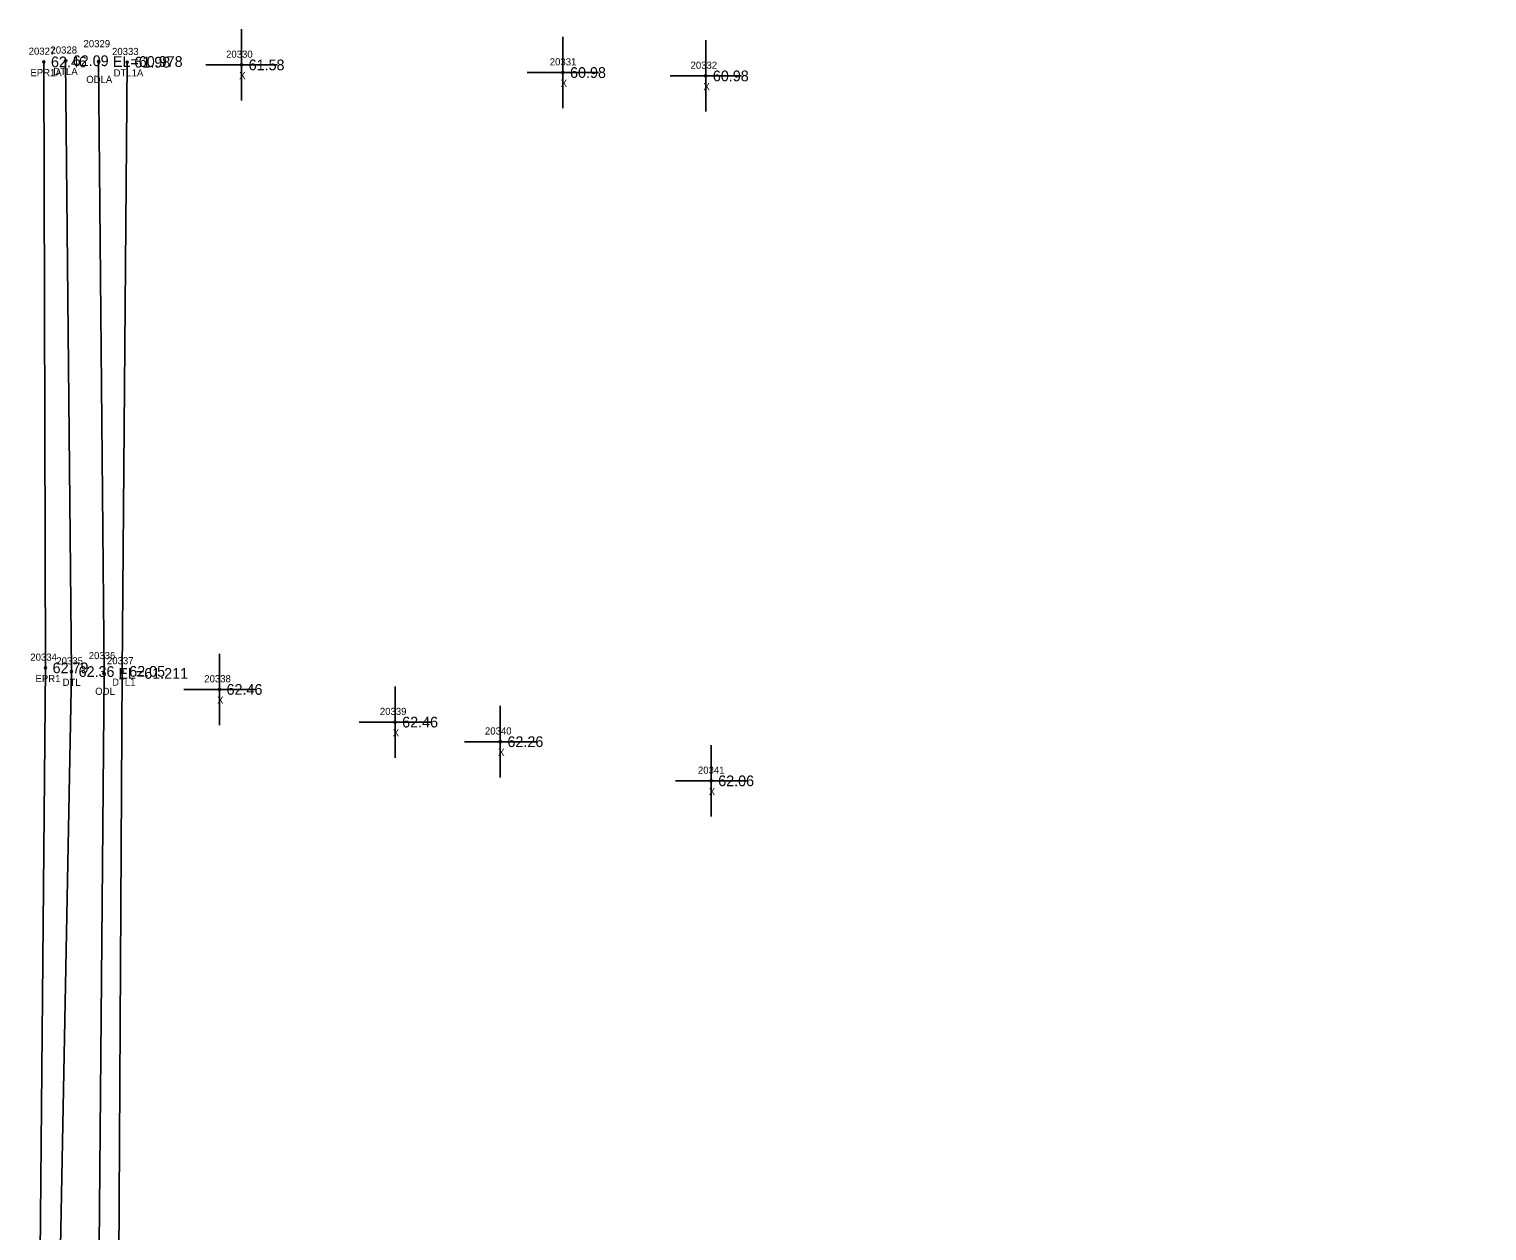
# Model space of a CAD drawing. Extents: x 2420351 to 2422725, y 845330 to 846558.
# Drawn here: x 2420970.4 to 2421174.5, y 846026.9 to 846195 of the extents above; entities that cross this region are included whole.
import ezdxf

# ---------------------------------------------------------------- set-up
doc = ezdxf.new("R2010")
doc.units = 0
for name, color, linetype in [('RD_EX_H2O', 7, 'Continuous'), ('RD_EX_H2O_txCode', 7, 'Continuous'), ('RD_EX_Misc', 7, 'Continuous'), ('RD_EX_Misc_txCode', 7, 'Continuous'), ('RD_EX_Road', 7, 'Continuous'), ('RD_EX_Road_txCode', 7, 'Continuous'), ('RD_EX_TX_H2O_ELEV', 7, 'Continuous'), ('RD_EX_TX_Misc_ELEV', 7, 'Continuous'), ('RD_EX_TX_Road_ELEV', 7, 'Continuous'), ('RD_SMD_Locator', 7, 'Continuous')]:
    doc.layers.add(name, color=color, linetype=linetype)

msp = doc.modelspace()

# ---------------------------------------------------------------- linework, layer by layer
at = {"layer": 'RD_EX_H2O'}
for points in [[(2420975.55, 846190.58), (2420976.37, 846105.11), (2420974.31, 845997.82), (2420976.03, 845896.74), (2420974.59, 845794.18), (2420975.37, 845743.63), (2420984.12, 845720.99), (2420999.91, 845711.18), (2421116.7, 845699.77), (2421177.35, 845696.01), (2421236.57, 845694.11), (2421292.07, 845694.75), (2421349.67, 845700.43), (2421411.57, 845706.56), (2421470.63, 845718.76), (2421529.96, 845732.93), (2421551.14, 845737.51), (2421602.97, 845753.33), (2421656.85, 845776.48), (2421724.45, 845805.15), (2421739.21, 845812.56)], [(2420980.17, 846190.47), (2420980.93, 846104.85), (2420980.02, 845997.99), (2420979.17, 845896.92), (2420978.72, 845794), (2420978.72, 845743.89), (2420987.58, 845724.3), (2421000.53, 845717.13), (2421117.24, 845704.33), (2421178.3, 845699.94), (2421237.1, 845697.97), (2421292.37, 845698.66), (2421349.43, 845702.84), (2421410.88, 845710.25), (2421469.94, 845721.7), (2421529.19, 845736.54), (2421550.26, 845742.27), (2421602, 845757.38), (2421655.89, 845778.44), (2421721.41, 845810.89), (2421742.22, 845823.45)], [(2420984.17, 846190.38), (2420983.45, 846105.14), (2420982.87, 845998.03), (2420982.41, 845897.21), (2420981.52, 845793.93), (2420982.23, 845744.07), (2420990.87, 845727.81), (2421002.71, 845721.72), (2421118.19, 845709.67), (2421178.8, 845706.59), (2421237.43, 845704.42), (2421292.29, 845705.88), (2421348.44, 845711.4), (2421408.11, 845718.43)]]:
    msp.add_lwpolyline(points, dxfattribs=at)
at = {"layer": 'RD_EX_Misc'}
for p, q in [((2421000.17, 846185), (2421000.17, 846195)), ((2421045.16, 846183.93), (2421045.16, 846193.93)), ((2421065.15, 846183.46), (2421065.15, 846193.46)), ((2420995.17, 846190), (2421005.17, 846190)), ((2421040.16, 846188.93), (2421050.16, 846188.93)), ((2421060.15, 846188.46), (2421070.15, 846188.46)), ((2420997.08, 846097.61), (2420997.08, 846107.61)), ((2420992.08, 846102.61), (2421002.08, 846102.61)), ((2421021.66, 846093.04), (2421021.66, 846103.04)), ((2421036.4, 846090.3), (2421036.4, 846100.3)), ((2421016.66, 846098.04), (2421026.66, 846098.04)), ((2421031.4, 846095.3), (2421041.4, 846095.3)), ((2421065.9, 846084.82), (2421065.9, 846094.82)), ((2421060.9, 846089.82), (2421070.9, 846089.82))]:
    msp.add_line(p, q, dxfattribs=at)
at = {"layer": 'RD_EX_Road'}
msp.add_lwpolyline([(2420972.5, 846190.42), (2420972.73, 846105.63), (2420971.77, 845998.07), (2420972.4, 845896.57), (2420972.04, 845794.22), (2420971.47, 845746.74), (2420974.33, 845731.55), (2420982.05, 845718.86), (2420998.34, 845708.25)], dxfattribs=at)
at = {"layer": 'RD_SMD_Locator'}
for centre in [(2420972.5, 846190.42), (2420975.55, 846190.58), (2420980.17, 846190.47), (2420984.17, 846190.38), (2421000.17, 846190), (2421045.16, 846188.93), (2421065.15, 846188.46), (2420972.73, 846105.63), (2420976.37, 846105.11), (2420980.93, 846104.85), (2420983.45, 846105.14), (2420997.08, 846102.61), (2421021.66, 846098.04), (2421036.4, 846095.3), (2421065.9, 846089.82)]:
    msp.add_circle(centre, 0.15, dxfattribs=at)

# ---------------------------------------------------------------- texts
at = {"layer": 'RD_EX_H2O_txCode'}
for s, p in [('20329', (2420978.06, 846192.47)), ('20328', (2420973.43, 846191.58)), ('20333', (2420982.05, 846191.38)), ('DTLA', (2420973.82, 846188.58)), ('DTL1A', (2420982.27, 846188.38)), ('ODLA', (2420978.44, 846187.47)), ('20336', (2420978.79, 846106.85)), ('20335', (2420974.25, 846106.11)), ('20337', (2420981.34, 846106.14)), ('DTL', (2420975.13, 846103.11)), ('DTL1', (2420982.05, 846103.14)), ('ODL', (2420979.69, 846101.85))]:
    msp.add_text(s, height=1, dxfattribs=at).set_placement(p)
at = {"layer": 'RD_EX_Misc_txCode'}
for s, p in [('20330', (2420998.01, 846191)), ('20331', (2421043.32, 846189.93)), ('20332', (2421063.03, 846189.46)), ('X', (2420999.85, 846188)), ('X', (2421044.84, 846186.93)), ('X', (2421064.83, 846186.46)), ('20338', (2420994.96, 846103.61)), ('X', (2420996.76, 846100.61)), ('20339', (2421019.54, 846099.04)), ('X', (2421021.34, 846096.04)), ('20340', (2421034.25, 846096.3)), ('X', (2421036.09, 846093.3)), ('20341', (2421064.06, 846090.82)), ('X', (2421065.58, 846087.82))]:
    msp.add_text(s, height=1, dxfattribs=at).set_placement(p)
at = {"layer": 'RD_EX_Road_txCode'}
for s, p in [('20327', (2420970.38, 846191.42)), ('EPR1A', (2420970.62, 846188.42)), ('20334', (2420970.61, 846106.63)), ('EPR1', (2420971.33, 846103.63))]:
    msp.add_text(s, height=1, dxfattribs=at).set_placement(p)
at = {"layer": 'RD_EX_TX_H2O_ELEV'}
for s, p in [('62.09', (2420976.55, 846189.83)), ('EL=60.978', (2420982.17, 846189.72)), ('61.98', (2420985.17, 846189.63)), ('62.36', (2420977.37, 846104.36)), ('62.05', (2420984.45, 846104.39)), ('EL=61.211', (2420982.93, 846104.1))]:
    msp.add_text(s, height=1.5, dxfattribs=at).set_placement(p)
at = {"layer": 'RD_EX_TX_Misc_ELEV'}
for s, p in [('61.58', (2421001.17, 846189.25)), ('60.98', (2421046.16, 846188.18)), ('60.98', (2421066.15, 846187.71)), ('62.46', (2420998.08, 846101.86)), ('62.46', (2421022.66, 846097.29)), ('62.26', (2421037.4, 846094.55)), ('62.06', (2421066.9, 846089.07))]:
    msp.add_text(s, height=1.5, dxfattribs=at).set_placement(p)
at = {"layer": 'RD_EX_TX_Road_ELEV'}
for s, p in [('62.46', (2420973.5, 846189.67)), ('62.79', (2420973.73, 846104.88))]:
    msp.add_text(s, height=1.5, dxfattribs=at).set_placement(p)

doc.saveas('drawing.dxf')
